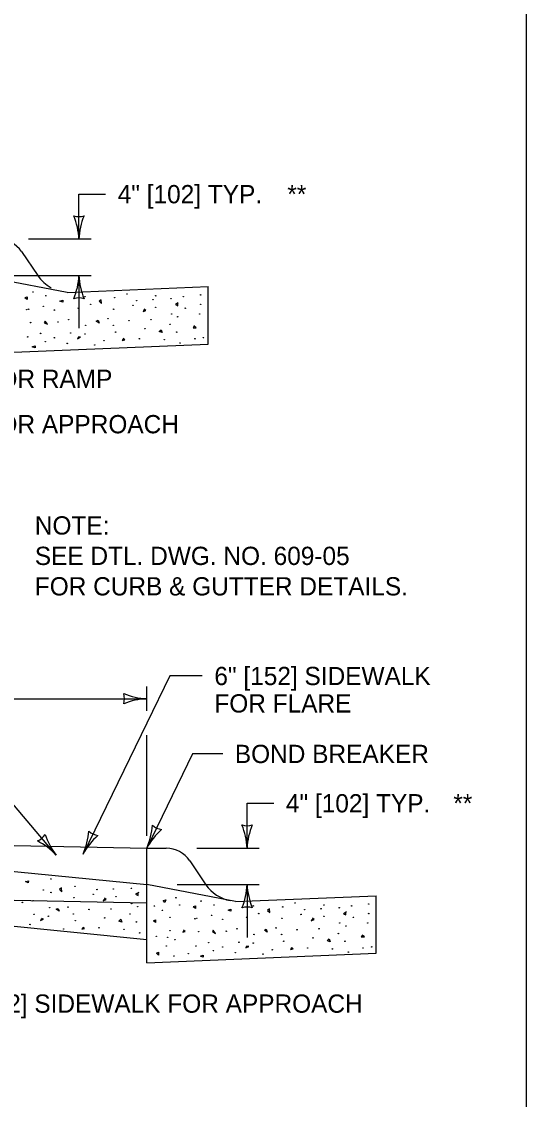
# Model space of a CAD drawing. Extents: x 49987.9 to 50021, y 49987.6 to 50011.4.
# Drawn here: x 50006.956 to 50008.615, y 50003.186 to 50006.728 of the extents above; entities that cross this region are included whole.
import ezdxf

# ---------------------------------------------------------------- set-up
doc = ezdxf.new("R2010")
doc.units = 0
for name, color, linetype in [('Level 1', 7, 'Continuous'), ('Level 2', 7, 'Continuous'), ('Level 3', 7, 'Continuous'), ('Level 4', 7, 'Continuous')]:
    doc.layers.add(name, color=color, linetype=linetype)

msp = doc.modelspace()

# ---------------------------------------------------------------- linework, layer by layer
at = {"layer": 'Level 1'}
for p, q in [((50006.9558, 50005.9717), (50007.0091, 50005.8928)), ((50007.1057, 50005.8376), (50006.8149, 50005.8932)), ((50007.1057, 50005.8376), (50007.5685, 50005.8567)), ((50007.5685, 50005.6679), (50007.5685, 50005.8567)), ((50007.0817, 50005.8092), (50007.0912, 50005.8123)), ((50007.0817, 50005.8092), (50007.0912, 50005.8123)), ((50007.0912, 50005.8061), (50007.0817, 50005.8092)), ((50007.0912, 50005.8061), (50007.0817, 50005.8092)), ((50007.0912, 50005.8123), (50007.0912, 50005.8061)), ((50007.0912, 50005.8123), (50007.0912, 50005.8061)), ((50007.2011, 50005.7434), (50007.2073, 50005.7464)), ((50007.2011, 50005.7434), (50007.2073, 50005.7464)), ((50007.2104, 50005.7371), (50007.2011, 50005.7434)), ((50007.2104, 50005.7371), (50007.2011, 50005.7434)), ((50007.2073, 50005.7464), (50007.2104, 50005.7371)), ((50007.2073, 50005.7464), (50007.2104, 50005.7371)), ((50007.408, 50005.7088), (50007.4144, 50005.715)), ((50007.408, 50005.7088), (50007.4144, 50005.715)), ((50007.4175, 50005.7056), (50007.408, 50005.7088)), ((50007.4175, 50005.7056), (50007.408, 50005.7088)), ((50007.4144, 50005.715), (50007.4175, 50005.7056)), ((50007.4144, 50005.715), (50007.4175, 50005.7056)), ((50006.8149, 50005.6366), (50007.5685, 50005.6679)), ((50006.9908, 50005.6586), (50007.0002, 50005.6618)), ((50006.9908, 50005.6586), (50007.0002, 50005.6618)), ((50007.0002, 50005.6554), (50006.9908, 50005.6586)), ((50007.0002, 50005.6554), (50006.9908, 50005.6586)), ((50007.0002, 50005.6618), (50007.0002, 50005.6554)), ((50007.0002, 50005.6618), (50007.0002, 50005.6554)), ((50005.8615, 50004.0421), (50007.3675, 50003.8919)), ((50005.8615, 50004.0421), (50007.3675, 50004.0119)), ((50007.3675, 50004.0119), (50007.4313, 50004.0119)), ((50007.3675, 50003.6353), (50007.3675, 50004.0119)), ((50007.5084, 50003.9703), (50007.5617, 50003.8914)), ((50006.9687, 50003.9017), (50006.9784, 50003.9041)), ((50006.9687, 50003.9017), (50006.9784, 50003.9041)), ((50006.978, 50003.8979), (50006.9687, 50003.9017)), ((50006.978, 50003.8979), (50006.9687, 50003.9017)), ((50006.9784, 50003.9041), (50006.978, 50003.8979)), ((50006.9784, 50003.9041), (50006.978, 50003.8979)), ((50005.8615, 50003.8621), (50007.3675, 50003.7119)), ((50007.6583, 50003.8363), (50007.3675, 50003.8919)), ((50007.4209, 50003.8393), (50007.4303, 50003.8424)), ((50007.4209, 50003.8393), (50007.4303, 50003.8424)), ((50007.4271, 50003.833), (50007.4209, 50003.8393)), ((50007.4271, 50003.833), (50007.4209, 50003.8393)), ((50007.4303, 50003.8424), (50007.4271, 50003.833)), ((50007.4303, 50003.8424), (50007.4271, 50003.833)), ((50007.6583, 50003.8363), (50008.1211, 50003.8554)), ((50008.1211, 50003.6666), (50008.1211, 50003.8554)), ((50007.0697, 50003.8108), (50007.076, 50003.8137)), ((50007.0697, 50003.8108), (50007.076, 50003.8137)), ((50007.0789, 50003.8044), (50007.0697, 50003.8108)), ((50007.0789, 50003.8044), (50007.0697, 50003.8108)), ((50007.076, 50003.8137), (50007.0789, 50003.8044)), ((50007.076, 50003.8137), (50007.0789, 50003.8044)), ((50007.6343, 50003.8079), (50007.6438, 50003.811)), ((50007.6343, 50003.8079), (50007.6438, 50003.811)), ((50007.6438, 50003.8048), (50007.6343, 50003.8079)), ((50007.6438, 50003.8048), (50007.6343, 50003.8079)), ((50007.6438, 50003.811), (50007.6438, 50003.8048)), ((50007.6438, 50003.811), (50007.6438, 50003.8048)), ((50007.2759, 50003.7722), (50007.2824, 50003.7782)), ((50007.2759, 50003.7722), (50007.2824, 50003.7782)), ((50007.2853, 50003.7688), (50007.2759, 50003.7722)), ((50007.2853, 50003.7688), (50007.2759, 50003.7722)), ((50007.2824, 50003.7782), (50007.2853, 50003.7688)), ((50007.2824, 50003.7782), (50007.2853, 50003.7688)), ((50007.3896, 50003.7733), (50007.3959, 50003.7765)), ((50007.3896, 50003.7733), (50007.3959, 50003.7765)), ((50007.3959, 50003.7671), (50007.3896, 50003.7733)), ((50007.3959, 50003.7671), (50007.3896, 50003.7733)), ((50007.3959, 50003.7765), (50007.3959, 50003.7671)), ((50007.3959, 50003.7765), (50007.3959, 50003.7671)), ((50007.7537, 50003.7421), (50007.7599, 50003.7451)), ((50007.7537, 50003.7421), (50007.7599, 50003.7451)), ((50007.763, 50003.7358), (50007.7537, 50003.7421)), ((50007.763, 50003.7358), (50007.7537, 50003.7421)), ((50007.7599, 50003.7451), (50007.763, 50003.7358)), ((50007.7599, 50003.7451), (50007.763, 50003.7358)), ((50007.9606, 50003.7075), (50007.967, 50003.7137)), ((50007.9606, 50003.7075), (50007.967, 50003.7137)), ((50007.9701, 50003.7043), (50007.9606, 50003.7075)), ((50007.9701, 50003.7043), (50007.9606, 50003.7075)), ((50007.967, 50003.7137), (50007.9701, 50003.7043)), ((50007.967, 50003.7137), (50007.9701, 50003.7043)), ((50007.3675, 50003.6353), (50008.1211, 50003.6666)), ((50007.399, 50003.6666), (50007.4053, 50003.6699)), ((50007.399, 50003.6666), (50007.4053, 50003.6699)), ((50007.4053, 50003.6605), (50007.399, 50003.6666)), ((50007.4053, 50003.6605), (50007.399, 50003.6666)), ((50007.4053, 50003.6699), (50007.4053, 50003.6605)), ((50007.4053, 50003.6699), (50007.4053, 50003.6605)), ((50007.5434, 50003.6573), (50007.5528, 50003.6605)), ((50007.5434, 50003.6573), (50007.5528, 50003.6605)), ((50007.5528, 50003.6541), (50007.5434, 50003.6573)), ((50007.5528, 50003.6541), (50007.5434, 50003.6573)), ((50007.5528, 50003.6605), (50007.5528, 50003.6541)), ((50007.5528, 50003.6605), (50007.5528, 50003.6541))]:
    msp.add_line(p, q, dxfattribs=at)
msp.add_lwpolyline([(50008.6146, 50011.2628), (50000.3356, 50011.2628), (50000.3356, 50000.0624), (50008.6146, 50000.0624)], close=True, dxfattribs=at)
for points in [[(50006.9677, 50005.8214), (50006.9747, 50005.8232), (50006.9747, 50005.8144), (50006.967, 50005.8201)], [(50006.9677, 50005.8214), (50006.9747, 50005.8232), (50006.9747, 50005.8144), (50006.967, 50005.8201)], [(50007.2173, 50005.8138), (50007.211, 50005.8087), (50007.2185, 50005.8016), (50007.2173, 50005.8138)], [(50007.2173, 50005.8138), (50007.211, 50005.8087), (50007.2185, 50005.8016), (50007.2173, 50005.8138)], [(50007.3601, 50005.7823), (50007.3549, 50005.7747), (50007.3645, 50005.7785), (50007.3588, 50005.7831)], [(50007.3601, 50005.7823), (50007.3549, 50005.7747), (50007.3645, 50005.7785), (50007.3588, 50005.7831)], [(50007.4708, 50005.8035), (50007.4611, 50005.7978), (50007.4689, 50005.7939), (50007.4689, 50005.8016)], [(50007.4708, 50005.8035), (50007.4611, 50005.7978), (50007.4689, 50005.7939), (50007.4689, 50005.8016)], [(50007.033, 50005.7434), (50007.0305, 50005.7376), (50007.0407, 50005.7331), (50007.033, 50005.7434)], [(50007.033, 50005.7434), (50007.0305, 50005.7376), (50007.0407, 50005.7331), (50007.033, 50005.7434)], [(50007.5233, 50005.7275), (50007.5194, 50005.7217), (50007.5297, 50005.7217), (50007.5219, 50005.7275)], [(50007.5233, 50005.7275), (50007.5194, 50005.7217), (50007.5297, 50005.7217), (50007.5219, 50005.7275)], [(50007.1425, 50005.6909), (50007.1398, 50005.6851), (50007.1494, 50005.6902), (50007.1431, 50005.6915)], [(50007.1425, 50005.6909), (50007.1398, 50005.6851), (50007.1494, 50005.6902), (50007.1431, 50005.6915)], [(50007.2903, 50005.6858), (50007.2864, 50005.6799), (50007.2955, 50005.682), (50007.2897, 50005.6858)], [(50007.2903, 50005.6858), (50007.2864, 50005.6799), (50007.2955, 50005.682), (50007.2897, 50005.6858)], [(50007.0873, 50003.8809), (50007.0809, 50003.8759), (50007.0883, 50003.8687), (50007.0873, 50003.8809)], [(50007.0873, 50003.8809), (50007.0809, 50003.8759), (50007.0883, 50003.8687), (50007.0873, 50003.8809)], [(50007.3406, 50003.8656), (50007.3307, 50003.8601), (50007.3385, 50003.856), (50007.3386, 50003.8637)], [(50007.3406, 50003.8656), (50007.3307, 50003.8601), (50007.3385, 50003.856), (50007.3386, 50003.8637)], [(50007.2295, 50003.8466), (50007.2241, 50003.8391), (50007.2338, 50003.8427), (50007.2282, 50003.8474)], [(50007.2295, 50003.8466), (50007.2241, 50003.8391), (50007.2338, 50003.8427), (50007.2282, 50003.8474)], [(50007.5203, 50003.8201), (50007.5273, 50003.8219), (50007.5273, 50003.8131), (50007.5196, 50003.8188)], [(50007.5203, 50003.8201), (50007.5273, 50003.8219), (50007.5273, 50003.8131), (50007.5196, 50003.8188)], [(50007.7699, 50003.8125), (50007.7636, 50003.8074), (50007.7711, 50003.8003), (50007.7699, 50003.8125)], [(50007.7699, 50003.8125), (50007.7636, 50003.8074), (50007.7711, 50003.8003), (50007.7699, 50003.8125)], [(50008.0234, 50003.8022), (50008.0137, 50003.7965), (50008.0215, 50003.7926), (50008.0215, 50003.8003)], [(50008.0234, 50003.8022), (50008.0137, 50003.7965), (50008.0215, 50003.7926), (50008.0215, 50003.8003)], [(50007.0215, 50003.7796), (50007.0184, 50003.774), (50007.0283, 50003.7784), (50007.0221, 50003.7801)], [(50007.0215, 50003.7796), (50007.0184, 50003.774), (50007.0283, 50003.7784), (50007.0221, 50003.7801)], [(50007.9127, 50003.781), (50007.9075, 50003.7734), (50007.9171, 50003.7772), (50007.9114, 50003.7818)], [(50007.9127, 50003.781), (50007.9075, 50003.7734), (50007.9171, 50003.7772), (50007.9114, 50003.7818)], [(50007.1578, 50003.7515), (50007.1537, 50003.7457), (50007.1629, 50003.7476), (50007.1572, 50003.7515)], [(50007.1578, 50003.7515), (50007.1537, 50003.7457), (50007.1629, 50003.7476), (50007.1572, 50003.7515)], [(50007.4895, 50003.7427), (50007.4852, 50003.7356), (50007.4933, 50003.7376), (50007.4877, 50003.7427)], [(50007.4895, 50003.7427), (50007.4852, 50003.7356), (50007.4933, 50003.7376), (50007.4877, 50003.7427)], [(50007.5856, 50003.7421), (50007.5831, 50003.7363), (50007.5933, 50003.7318), (50007.5856, 50003.7421)], [(50007.5856, 50003.7421), (50007.5831, 50003.7363), (50007.5933, 50003.7318), (50007.5856, 50003.7421)], [(50008.0759, 50003.7262), (50008.072, 50003.7204), (50008.0823, 50003.7204), (50008.0745, 50003.7262)], [(50008.0759, 50003.7262), (50008.072, 50003.7204), (50008.0823, 50003.7204), (50008.0745, 50003.7262)], [(50007.6951, 50003.6896), (50007.6924, 50003.6838), (50007.702, 50003.6889), (50007.6957, 50003.6902)], [(50007.6951, 50003.6896), (50007.6924, 50003.6838), (50007.702, 50003.6889), (50007.6957, 50003.6902)], [(50007.8429, 50003.6845), (50007.839, 50003.6786), (50007.8481, 50003.6807), (50007.8423, 50003.6845)], [(50007.8429, 50003.6845), (50007.839, 50003.6786), (50007.8481, 50003.6807), (50007.8423, 50003.6845)]]:
    msp.add_lwpolyline(points, dxfattribs=at)
for centre in [(50006.9932, 50005.839), (50006.9932, 50005.839), (50007.0356, 50005.8266), (50007.0356, 50005.8266), (50007.1643, 50005.8234), (50007.1643, 50005.8234), (50007.2616, 50005.8203), (50007.2616, 50005.8203), (50007.302, 50005.8326), (50007.302, 50005.8326), (50007.3337, 50005.8109), (50007.3337, 50005.8109), (50007.3874, 50005.8139), (50007.3874, 50005.8139), (50007.3965, 50005.8266), (50007.3965, 50005.8266), (50007.4469, 50005.8171), (50007.4469, 50005.8171), (50007.4875, 50005.8234), (50007.4875, 50005.8234), (50007.544, 50005.8297), (50007.544, 50005.8297), (50006.9726, 50005.7811), (50006.9726, 50005.7811), (50006.9791, 50005.7826), (50006.9791, 50005.7826), (50007.0274, 50005.7921), (50007.0274, 50005.7921), (50007.0639, 50005.7795), (50007.0639, 50005.7795), (50007.1423, 50005.7858), (50007.1826, 50005.7983), (50007.1826, 50005.7983), (50007.2584, 50005.7826), (50007.2584, 50005.7826), (50007.3217, 50005.7951), (50007.3217, 50005.7951), (50007.3965, 50005.7889), (50007.3965, 50005.7889), (50007.4938, 50005.7858), (50007.4938, 50005.7858), (50007.5442, 50005.7983), (50007.5442, 50005.7983), (50006.9854, 50005.7387), (50006.9854, 50005.7387), (50007.0759, 50005.7404), (50007.0759, 50005.7404), (50007.1109, 50005.7481), (50007.1109, 50005.7481), (50007.2396, 50005.7512), (50007.2396, 50005.7512), (50007.3086, 50005.745), (50007.3086, 50005.745), (50007.3808, 50005.7481), (50007.3808, 50005.7481), (50007.4487, 50005.767), (50007.4487, 50005.767), (50007.4687, 50005.7575), (50007.4687, 50005.7575), (50007.5409, 50005.7669), (50007.5409, 50005.7669), (50007.0182, 50005.7028), (50007.0182, 50005.7028), (50007.1172, 50005.7042), (50007.1172, 50005.7042), (50007.1643, 50005.701), (50007.1643, 50005.701), (50007.1667, 50005.7294), (50007.1667, 50005.7294), (50007.2575, 50005.7294), (50007.2575, 50005.7294), (50007.2647, 50005.7073), (50007.2647, 50005.7073), (50007.361, 50005.7185), (50007.361, 50005.7185), (50007.444, 50005.7325), (50007.444, 50005.7325), (50007.4655, 50005.7073), (50007.4655, 50005.7073), (50006.976, 50005.6916), (50006.976, 50005.6916), (50007.0337, 50005.6762), (50007.0337, 50005.6762), (50007.0639, 50005.6885), (50007.0639, 50005.6885), (50007.1057, 50005.6699), (50007.1057, 50005.6699), (50007.1965, 50005.6648), (50007.1965, 50005.6648), (50007.227, 50005.6791), (50007.227, 50005.6791), (50007.3432, 50005.6853), (50007.3432, 50005.6853), (50007.4247, 50005.6822), (50007.4247, 50005.6822), (50007.4769, 50005.6715), (50007.4769, 50005.6715), (50007.5252, 50005.6853), (50007.5252, 50005.6853), (50007.5535, 50005.6887), (50007.5535, 50005.6887), (50007.0521, 50003.9103), (50007.0521, 50003.9103), (50007.0276, 50003.8742), (50007.0276, 50003.8742), (50007.0523, 50003.8661), (50007.0523, 50003.8661), (50007.1317, 50003.8865), (50007.1317, 50003.8865), (50007.1913, 50003.8602), (50007.1913, 50003.8602), (50007.2037, 50003.8757), (50007.2037, 50003.8757), (50007.2574, 50003.8777), (50007.2574, 50003.8777), (50007.317, 50003.8797), (50007.317, 50003.8797), (50006.9584, 50003.8334), (50006.9584, 50003.8334), (50006.9938, 50003.8388), (50006.9938, 50003.8388), (50007.1278, 50003.8489), (50007.1278, 50003.8489), (50007.266, 50003.8525), (50007.266, 50003.8525), (50007.3178, 50003.8295), (50007.3178, 50003.8295), (50007.3924, 50003.822), (50007.3924, 50003.822), (50007.4628, 50003.8486), (50007.4628, 50003.8486), (50007.4752, 50003.8252), (50007.4752, 50003.8252), (50007.5458, 50003.8376), (50007.5458, 50003.8376), (50007.5882, 50003.8252), (50007.5882, 50003.8252), (50007.7169, 50003.8221), (50007.7169, 50003.8221), (50007.8546, 50003.8313), (50007.8546, 50003.8313), (50007.9491, 50003.8252), (50007.9491, 50003.8252), (50008.0401, 50003.8221), (50008.0401, 50003.8221), (50008.0966, 50003.8284), (50008.0966, 50003.8284), (50006.9971, 50003.7945), (50006.9971, 50003.7945), (50007.0439, 50003.7882), (50007.0439, 50003.7882), (50007.0482, 50003.8164), (50007.0482, 50003.8164), (50007.1084, 50003.8179), (50007.1084, 50003.8179), (50007.1259, 50003.7957), (50007.1259, 50003.7957), (50007.1773, 50003.8103), (50007.1773, 50003.8103), (50007.2495, 50003.812), (50007.2495, 50003.812), (50007.3124, 50003.7952), (50007.3124, 50003.7952), (50007.3376, 50003.8197), (50007.3376, 50003.8197), (50007.4188, 50003.8074), (50007.4188, 50003.8074), (50007.58, 50003.7908), (50007.58, 50003.7908), (50007.7352, 50003.7969), (50007.7352, 50003.7969), (50007.8141, 50003.8189), (50007.8141, 50003.8189), (50007.8743, 50003.7938), (50007.8743, 50003.7938), (50007.8863, 50003.8095), (50007.8863, 50003.8095), (50007.94, 50003.8126), (50007.94, 50003.8126), (50007.9491, 50003.7876), (50007.9491, 50003.7876), (50007.9995, 50003.8157), (50007.9995, 50003.8157), (50008.0967, 50003.7969), (50008.0967, 50003.7969), (50006.9834, 50003.7611), (50006.9834, 50003.7611), (50007.1326, 50003.7735), (50007.1326, 50003.7735), (50007.2291, 50003.7828), (50007.2291, 50003.7828), (50007.3334, 50003.7695), (50007.3334, 50003.7695), (50007.4438, 50003.7844), (50007.4438, 50003.7844), (50007.5252, 50003.7797), (50007.5252, 50003.7797), (50007.5317, 50003.7813), (50007.5317, 50003.7813), (50007.6164, 50003.7781), (50007.6164, 50003.7781), (50007.6949, 50003.7844), (50007.811, 50003.7813), (50007.811, 50003.7813), (50008.0013, 50003.7657), (50008.0013, 50003.7657), (50008.0213, 50003.7562), (50008.0213, 50003.7562), (50008.0464, 50003.7844), (50008.0464, 50003.7844), (50008.0934, 50003.7656), (50008.0934, 50003.7656), (50007.0944, 50003.746), (50007.0944, 50003.746), (50007.2106, 50003.75), (50007.2106, 50003.75), (50007.2921, 50003.7452), (50007.2921, 50003.7452), (50007.344, 50003.7335), (50007.344, 50003.7335), (50007.3986, 50003.7218), (50007.3986, 50003.7218), (50007.4362, 50003.7187), (50007.4362, 50003.7187), (50007.4438, 50003.7405), (50007.4438, 50003.7405), (50007.538, 50003.7374), (50007.538, 50003.7374), (50007.6285, 50003.739), (50007.6285, 50003.739), (50007.6635, 50003.7468), (50007.6635, 50003.7468), (50007.7193, 50003.7281), (50007.7193, 50003.7281), (50007.7922, 50003.7499), (50007.7922, 50003.7499), (50007.8101, 50003.7281), (50007.8101, 50003.7281), (50007.8612, 50003.7436), (50007.8612, 50003.7436), (50007.9136, 50003.7171), (50007.9136, 50003.7171), (50007.9334, 50003.7468), (50007.9334, 50003.7468), (50007.9966, 50003.7312), (50007.9966, 50003.7312), (50007.4313, 50003.6903), (50007.4313, 50003.6903), (50007.4595, 50003.7109), (50007.4595, 50003.7109), (50007.5286, 50003.6903), (50007.5286, 50003.6903), (50007.5708, 50003.7015), (50007.5708, 50003.7015), (50007.6164, 50003.6871), (50007.6164, 50003.6871), (50007.6698, 50003.7028), (50007.6698, 50003.7028), (50007.7169, 50003.6997), (50007.7169, 50003.6997), (50007.8173, 50003.706), (50007.8173, 50003.706), (50007.8957, 50003.684), (50007.8957, 50003.684), (50007.9773, 50003.6809), (50007.9773, 50003.6809), (50008.0181, 50003.706), (50008.0181, 50003.706), (50008.0777, 50003.684), (50008.0777, 50003.684), (50008.1061, 50003.6874), (50008.1061, 50003.6874), (50007.4563, 50003.6576), (50007.4563, 50003.6576), (50007.5035, 50003.6652), (50007.5035, 50003.6652), (50007.5863, 50003.6749), (50007.5863, 50003.6749), (50007.6583, 50003.6686), (50007.6583, 50003.6686), (50007.7491, 50003.6635), (50007.7491, 50003.6635), (50007.7796, 50003.6777), (50007.7796, 50003.6777), (50008.0295, 50003.6702), (50008.0295, 50003.6702)]:
    msp.add_circle(centre, 0.000763, dxfattribs=at)
for centre, radius, start, end in [((50006.8778, 50005.919), 0.0941, 33.983, 89.4567), ((50007.1129, 50005.9635), 0.1256, 214.2724, 241.5002), ((50007.4304, 50003.9177), 0.0941, 33.983, 89.4567), ((50007.6648, 50003.9628), 0.1255, 214.6549, 259.3631)]:
    msp.add_arc(centre, radius, start, end, dxfattribs=at)
at = {"layer": 'Level 3'}
for p, q in [((50007.1443, 50006.0132), (50007.1443, 50006.1605)), ((50007.1443, 50006.1605), (50007.2317, 50006.1605)), ((50006.9787, 50006.0132), (50007.1843, 50006.0132)), ((50006.9149, 50005.8932), (50007.1843, 50005.8932)), ((50007.1443, 50005.8932), (50007.1443, 50005.7198)), ((50007.4428, 50004.5774), (50007.3675, 50004.4225)), ((50007.5493, 50004.5774), (50007.4428, 50004.5774)), ((50007.3675, 50004.4625), (50007.3675, 50004.5429)), ((50005.8615, 50004.5029), (50007.3675, 50004.5029)), ((50007.3675, 50004.4225), (50007.1582, 50003.9923)), ((50007.3675, 50004.0519), (50007.3675, 50004.3825)), ((50007.518, 50004.3214), (50007.3675, 50004.0119)), ((50007.6166, 50004.3214), (50007.518, 50004.3214)), ((50007.0699, 50003.9883), (50006.8778, 50004.2145)), ((50007.6969, 50004.0119), (50007.6969, 50004.1592)), ((50007.6969, 50004.1592), (50007.7843, 50004.1592)), ((50007.5313, 50004.0119), (50007.7369, 50004.0119)), ((50007.4675, 50003.8919), (50007.7369, 50003.8919)), ((50007.6969, 50003.8919), (50007.6969, 50003.7184))]:
    msp.add_line(p, q, dxfattribs=at)
for centre in [(50007.1423, 50005.7858), (50007.6949, 50003.7844)]:
    msp.add_circle(centre, 0.000763, dxfattribs=at)
for centre, radius, start, end in [((50007.1443, 50006.1414), 0.0548, 252.1388, 287.8612), ((50006.9116, 50006.0017), 0.233, 2.8273, 22.0772), ((50007.3664, 50006.004), 0.2223, 157.456, 177.6395), ((50006.9221, 50005.9023), 0.2223, 337.456, 357.6395), ((50007.377, 50005.9047), 0.233, 182.8273, 202.0772), ((50007.1443, 50005.765), 0.0548, 72.1388, 107.8612), ((50007.3766, 50004.725), 0.2223, 247.456, 267.6395), ((50007.2392, 50004.5029), 0.0548, 342.1388, 17.8612), ((50007.3789, 50004.2701), 0.233, 92.8273, 112.0772), ((50007.1531, 50004.1033), 0.233, 336.8939, 356.1437), ((50007.5632, 50003.9065), 0.2223, 131.5226, 151.7061), ((50007.4235, 50004.1272), 0.0548, 226.2054, 261.9277), ((50007.6969, 50004.1401), 0.0548, 252.1388, 287.8612), ((50007.4641, 50004.0004), 0.233, 2.8273, 22.0772), ((50007.919, 50004.0027), 0.2223, 157.456, 177.6395), ((50006.9869, 50004.086), 0.0548, 292.464, 328.1863), ((50006.9064, 50003.8376), 0.2223, 42.6856, 62.8691), ((50007.2547, 50004.1301), 0.233, 198.248, 217.4978), ((50006.9439, 50004.0837), 0.233, 336.8939, 356.1437), ((50007.354, 50003.8869), 0.2223, 131.5226, 151.7061), ((50007.2143, 50004.1076), 0.0548, 226.2054, 261.9277), ((50007.4747, 50003.901), 0.2223, 337.456, 357.6395), ((50007.9296, 50003.9034), 0.233, 182.8273, 202.0772), ((50007.6969, 50003.7636), 0.0548, 72.1388, 107.8612)]:
    msp.add_arc(centre, radius, start, end, dxfattribs=at)
at = {"layer": 'Level 4'}
msp.add_line((50005.8615, 50003.8621), (50007.3675, 50003.832), dxfattribs=at)

# ---------------------------------------------------------------- texts
at = {"layer": 'Level 2'}
for s, p in [('4" [102] TYP.', (50007.2717, 50006.1305)), ('**', (50007.829, 50006.1308)), ('6" [152] SIDEWALK FOR RAMP', (50006.0978, 50005.5239)), ('6" [152] SIDEWALK FOR APPROACH', (50006.0978, 50005.3748)), ('NOTE:', (50006.9994, 50005.0421)), ('SEE DTL. DWG. NO. 609-05', (50006.9994, 50004.9421)), ('FOR CURB & GUTTER DETAILS.', (50006.9994, 50004.8421)), ('6" [152] SIDEWALK', (50007.5893, 50004.5474)), ('FOR FLARE', (50007.5893, 50004.4574)), ('BOND BREAKER', (50007.6566, 50004.2914)), ('4" [102] TYP.', (50007.8243, 50004.1292)), ('**', (50008.3744, 50004.1295)), ('6" [152] SIDEWALK FOR APPROACH', (50006.7017, 50003.471))]:
    msp.add_text(s, height=0.06, dxfattribs=at).set_placement(p)

doc.saveas('drawing.dxf')
